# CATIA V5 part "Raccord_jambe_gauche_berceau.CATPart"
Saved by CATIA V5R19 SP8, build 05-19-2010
Part number: Raccord_jambe_gauche_berceau
Bounding box of the stored display mesh (mm): x -900 to -555, y -1185 to -825, z -35 to 310
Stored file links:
  G:\EU_thinkMotion\CFAO_2010\MMS_groupe2\MMS_groupe2\OK\mmartini\mmartiniCFAO\Raccord_jambe_gauche_berceau.CATPart
  C:\Users\Mathieu Martini\Desktop\CFAO\Animation\CFAO.CATProduct
  G:\EU_thinkMotion\CFAO_2010\MMS_groupe2\MMS_groupe2\OK\mmartini\mmartiniCFAO\Squelette.CATPart
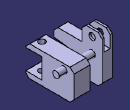
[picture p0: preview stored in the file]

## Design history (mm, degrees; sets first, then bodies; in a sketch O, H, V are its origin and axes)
External parameters (linked from other documents)
  External.diametre_canon = 150 mm
  External.diametre_verin = 120 mm
AxisSystem1: origin (0, 0, 0), X (1, 0, 0), Y (0, 1, 0), Z (0, 0, 1)
Set1
  Sketch1 on Plane1, origin (-675, 0, 0), H (0, 1, 0), V (0, 0, 1)
    line L1 (-825, 190) -> (-1185, 190)
    line L2 (-1185, 190) -> (-1185, -35)
    line L3 (-1185, -35) -> (-825, -35)
    line L4 (-825, -35) -> (-825, 190)
    reference projected point E1 (-900, 150) from Line1
    reference projected point E2 (-900, 150) from Point1
    distance E1 L1 = 40 {= External.diametre_verin /3}
    distance E2 L4 = 75 {= External.diametre_canon /2}
    distance L4 L2 = 360 {= External.diametre_verin *3}
    distance L1 L3 = 225 {= External.diametre_canon *1.5}
    horizontal: L1 H, L3 H
    vertical: L2 V, L4 V
Set2
  Plane1 "Plan_verin_gauche": linked copy from another document
  Line1 "axe_berceau_jambe": linked copy from another document
  Point1: linked copy from another document
  Plane2 "arret_berceau_ext_gauche": linked copy from another document
  Plane3 "arret_berceau_gauche": linked copy from another document
  Plane4 "Plan_rayon_ext_verin_gauche": linked copy from another document
  Plane5 "Plan_rayon_int_verin_gauche": linked copy from another document
Body1 (main body)
  Pad1: profile Sketch1, direction (1, 0, 0), up to Plane4, opposite side up to Plane5
  Sketch2 on Plane1, origin (-675, 0, 0), H (0, 1, 0), V (0, 0, 1)
    circle A1 centre (-900, 150) radius 24
    point P1 (-900, 150)
    reference projected point E1 (-900, 150) from Line1
    radius A1 = 24 {= External.diametre_verin /5}
    coincidence: P1 E1
  Pad2: profile Sketch2, direction (1, 0, 0), length 120 {= External.diametre_verin}, opposite side length 150 {= External.diametre_canon}
  Sketch3 on face of Pad1 from Sketch1.L1, origin (0, 0, 190), H (1, 0, 0), V (0, 1, 0)
    circle A1 centre (-675, -1125) radius 24
    point P1 (-675, -1125)
    reference projected line E1 through (0, -900) direction (1, 0) from Line1
    reference intersected line E2 through (-675, 0) direction (0, 1) from Plane1
    radius A1 = 24 {= External.diametre_verin /5}
    distance P1 E1 = 225 {= External.diametre_canon *1.5}
    coincidence: P1 E2
  Pocket1: profile Sketch3, direction (0, 0, -1), through (limit type 6)
  Sketch4 on face of Pad1 from Sketch1.L2, origin (0, -1185, 0), H (1, 0, 0), V (0, 0, 1)
    line L1 (-735, 152.5) -> (-615, 152.5)
    line L2 (-615, 152.5) -> (-615, 2.5)
    line L3 (-615, 2.5) -> (-735, 2.5)
    line L4 (-735, 2.5) -> (-735, 152.5)
    reference projected line E1 (-735, -35) -> (-615, -35) from edge [face of Pad1 from Sketch1.L3 | face of Pad1 from Sketch1.L2]
    reference projected line E2 (-735, 190) -> (-615, 190) from edge [face of Pad1 from Sketch1.L2 | face of Pad1 from Sketch1.L1]
    reference projected line E3 (-615, -35) -> (-615, 190) from edge [start face of Pad1 | face of Pad1 from Sketch1.L2]
    reference projected line E4 (-735, -35) -> (-735, 190) from edge [face of Pad1 from Sketch1.L2 | end face of Pad1]
    distance L3 E1 = 37.5 {= External.diametre_canon /4}
    distance L1 E2 = 37.5 {= External.diametre_canon /4}
    horizontal: L1 H, L3 H
    vertical: L2 V, L4 V
    coincidence: L2 E3, L4 E4
  Pocket2: profile Sketch4, direction (0, 1, 0), length 120 {= External.diametre_verin}
  Sketch5 on start face of Pad2, origin (-825, 0, 0), H (0, -1, 0), V (0, 0, 1)
    projected line E1 (1185, 190) -> (825, 190) from edge [face of Pad1 from Sketch1.L1 | end face of Pad1]
    projected line E2 (825, 190) -> (825, -35) from edge [face of Pad1 from Sketch1.L4 | end face of Pad1]
    projected line E3 (825, -35) -> (1185, -35) from edge [face of Pad1 from Sketch1.L3 | end face of Pad1]
    line L1 (1185, 190) -> (1185, -35)
    vertical: L1 V
  Pad3: profile Sketch5, direction (-1, 0, 0), length 75 {= External.diametre_canon /2}
  Sketch6 on face of Pad3 from Sketch5.E1, origin (0, 0, 190), H (1, 0, 0), V (0, 1, 0)
    line L1 (-900, -825) -> (-825, -825)
    line L2 (-825, -825) -> (-825, -975)
    line L3 (-825, -975) -> (-900, -975)
    line L4 (-900, -975) -> (-900, -825)
    reference projected line E1 (-825, -825) -> (-900, -825) from edge [face of Pad3 from Sketch5.E2 | face of Pad3 from Sketch5.E1]
    reference projected line E2 (-825, -1185) -> (-825, -825) from edge [start face of Pad3 | face of Pad3 from Sketch5.E1]
    reference projected line E3 (-900, -1185) -> (-900, -825) from edge [face of Pad3 from Sketch5.E1 | end face of Pad3]
    distance L1 L3 = 150 {= External.diametre_canon}
    horizontal: L1 H, L3 H
    vertical: L2 V, L4 V
    coincidence: L1 E1, L2 E2, L4 E3
  Pad4: profile Sketch6, direction (0, 0, 1), length 120 {= External.diametre_verin}
  Sketch7 on face of Pad4, origin (-900, 0, 0), H (0, -1, 0), V (0, 0, 1)
    line L1 (1185, 115) -> (1051.8689, 96.25)
    point P1 (1185, 115)
    point P2 (1051.8689, 96.25)
    line L2 (1051.8689, 58.75) -> (1051.8689, 96.25)
    line L3 (1051.8689, 58.75) -> (1185, 40)
    line L4 (1185, 40) -> (1185, 115)
    axis line L5 (1288.6135, 77.5) -> (1102.6761, 77.5)
    reference projected line E1 (1185, -35) -> (1185, 190) from edge [face of Pad3 from Sketch5.L1 | end face of Pad3]
    reference projected line E2 (825, -35) -> (1185, -35) from edge [face of Pad3 from Sketch5.E3 | face of Pad4]
    length L4 = 75 {= External.diametre_canon /2}
    length L2 = 37.5 {= External.diametre_canon /4}
    distance L4 L2 = 133.1311
    distance L5 P2 = 18.75 {= External.diametre_canon /8}
    distance L5 P1 = 37.5 {= External.diametre_canon /4}
    distance L5 E2 = 112.5 {= External.diametre_canon *0.75}
    vertical: L2 V, L4 V
    horizontal: L5 H
    coincidence: L4 E1
  Pocket3: profile Sketch7, direction (1, 0, 0), through (limit type 6)
  Sketch8 on end face of Pad4, origin (0, 0, 310), H (1, 0, 0), V (0, 1, 0)
    line L1 (-885, -825) -> (-840, -825)
    line L2 (-840, -825) -> (-840, -975)
    line L3 (-840, -975) -> (-885, -975)
    line L4 (-885, -975) -> (-885, -825)
    reference projected line E1 (-825, -825) -> (-900, -825) from edge [face of Pad4 | end face of Pad4]
    reference projected line E2 (-900, -975) -> (-825, -975) from edge [face of Pad4 from Sketch6.L3 | end face of Pad4]
    reference projected line E3 (-900, -825) -> (-900, -975) from edge [face of Pad4 | end face of Pad4]
    reference projected line E4 (-825, -975) -> (-825, -825) from edge [face of Pad4 | end face of Pad4]
    distance L4 E3 = 15 {= External.diametre_canon /10}
    distance E4 L2 = 15 {= External.diametre_canon /10}
    horizontal: L1 H, L3 H
    vertical: L2 V, L4 V
    coincidence: L1 E1, L3 E2
  Pocket4: profile Sketch8, direction (0, 0, -1), up to face of Pad3 from Sketch5.E1
  Sketch9 on face of Pad4, origin (-900, 0, 0), H (0, -1, 0), V (0, 0, 1)
    circle A1 centre (900, 260) radius 24
    point P1 (900, 260)
    reference projected line E1 (825, 310) -> (975, 310) from edge [face of Pad4 | end face of Pad4]
    reference projected point E2 (900, 150) from Line1
    distance P1 E1 = 50 {= External.diametre_canon /3}
    radius A1 = 24 {= External.diametre_verin /5}
    distance P1 E2 H = 0
  Pocket5: profile Sketch9, direction (1, 0, 0), through (limit type 3)
  Chamfer1: length 30 {= External.diametre_canon /5}, angle 45, on edge [face of Pad4 | end face of Pad4] (x2); edge [face of Pad4 from Sketch6.L3 | end face of Pad4] (x2); edge [face of Pad1 from Sketch1.L1 | face of Pad1 from Sketch1.L4]; edge [face of Pad1 from Sketch1.L2 | face of Pad1 from Sketch1.L1]; edge [face of Pad3 | face of Pad3 from Sketch5.L1]
  Chamfer2: length 24 {= External.diametre_verin /5}, angle 45, on edge [face of Pad3 from Sketch5.L1 | face of Pad3 from Sketch5.E3]; edge [face of Pad1 from Sketch1.L3 | face of Pad1 from Sketch1.L2]
  Chamfer3: length 30 {= External.diametre_canon /5}, angle 45, on edge [face of Pad3 from Sketch5.E3 | face of Pad4]; edge [face of Pad1 from Sketch1.L4 | face of Pad1 from Sketch1.L3]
